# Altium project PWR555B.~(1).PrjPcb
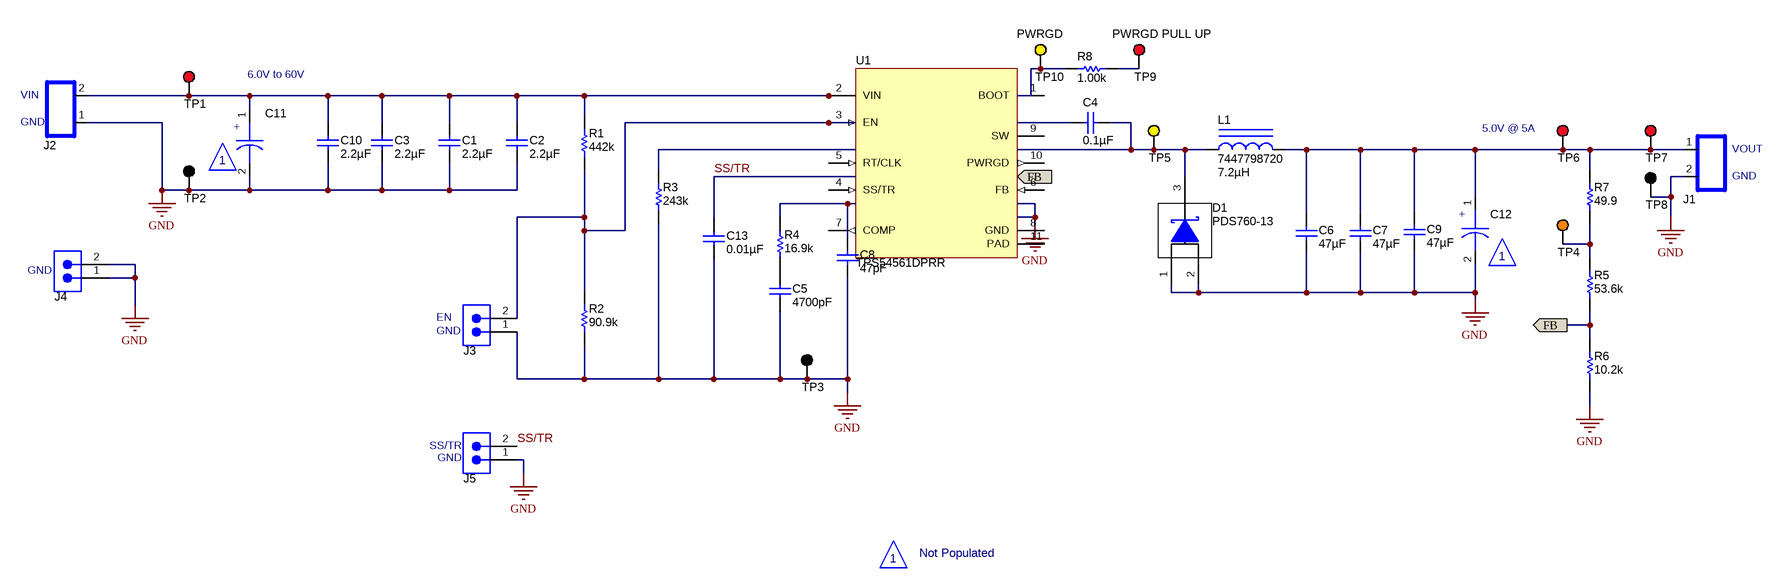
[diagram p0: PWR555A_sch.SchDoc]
CopyrightYear: 2013; PCB_Layout: Anthony Fagnani; PCB_Rev: A; PRJ_Customer: Public Release; PRJ_Engineer: Anthony Fagnani; PRJ_Number: PWR555; PRJ_Title: TPS54x61/x41EVM-555; SCH_Rev: A; TechSupport: http://www.ti.com/support
2 sheets, 58 parts. Net scope: flat (ports and power ports of the same name join across sheets).
Board file: PWR555A_pcb.PcbDoc
Sheets:
  PWR555A_sch.SchDoc
  PWR555A_hdwr.SchDoc

## Sheet PWR555A_sch.SchDoc
size 431 x 279 mm; Date: Not shown in title block; ApprovedBy: Not shown in title block; CheckedBy: Not shown in title block; Author: Not shown in title block; CompanyName: Not shown in title block; DrawnBy: Terry Dillard; Engineer: Steve Schnier; Organization: Not shown in title block; Address1: Not shown in title block; Address2: Not shown in title block; Address3: Not shown in title block; Address4: Not shown in title block; DocumentNumber: 1; Revision: Use project parameter SCH_Rev; SheetNumber: 1; SheetTotal: 2; PageSetup: Record=PageOptions¦CenterHorizontal=True¦CenterVertical=True¦PrintScale=1.00¦XCorrection=1.00¦YCorrection=1.00¦PrintKind=0¦BorderSize=5000000¦LeftOffset=0¦BottomOffset=0¦Orientation=2¦PaperLength=1000¦PaperWidth=1000¦Scale=100¦PaperSource=15¦PrintQuality=600¦MediaType=1¦DitherType=10¦PaperKind=Letter¦PrintScaleMode=1

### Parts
C1  ValueDisplayed: 2.2µF  [1210]  (hidden comment: GRM32ER72A225KA35L)
C2  ValueDisplayed: 2.2µF  [1210]  (hidden comment: GRM32ER72A225KA35L)
C3  ValueDisplayed: 2.2µF  [1210]  (hidden comment: GRM32ER72A225KA35L)
C4  ValueDisplayed: 0.1µF  [0603]  (hidden comment: C0603C104K8RACTU)
C5  ValueDisplayed: 4700pF  [0603]  (hidden comment: C0603C472J5RACTU)
C6  ValueDisplayed: 47µF  [1210]  (hidden comment: GRM32ER61C476ME15L)
C7  ValueDisplayed: 47µF  [1210]  (hidden comment: GRM32ER61C476ME15L)
C8  ValueDisplayed: 47pF  [0603]  (hidden comment: 06035A470JAT2A)
C9  ValueDisplayed: 47µF  [1210]  (hidden comment: GRM32ER61C476ME15L)
C10  ValueDisplayed: 2.2µF  [1210]  (hidden comment: GRM32ER72A225KA35L)
C11  Engineering Only  [C_SM-1210/E_TH-F]  (value not drawn)
C12  Engineering Only  [C_SM-1210/E_TH-F]  (value not drawn)
C13  ValueDisplayed: 0.01µF  [0603]  (hidden comment: C0603C103K5RACTU)
D1  PDS760-13  [PowerDI5]
J1  TBLK_15A_2X5.1MM  [TB_2X5.1MM]  (value not drawn)
J2  TBLK_15A_2X5.1MM  [TB_2X5.1MM]  (value not drawn)
J3  TSW-102-07-G-S  [TSW-102-07-G-S]  (value not drawn)
J4  TSW-102-07-G-S  [TSW-102-07-G-S]  (value not drawn)
J5  TSW-102-07-G-S  [TSW-102-07-G-S]  (value not drawn)
L1  7447798720  ValueDisplayed: 7.2µH  [WE-PDF_1064]
R1  value 442k  [0603]  (hidden comment: CRCW0603442KFKEA)
R2  value 90.9k  [0603]  (hidden comment: CRCW060390K9FKEA)
R3  value 243k  [0603]  (hidden comment: CRCW0603243KFKEA)
R4  value 16.9k  [0603]  (hidden comment: CRCW060316K9FKEA)
R5  value 53.6k  [0603]  (hidden comment: CRCW060353K6FKEA)
R6  value 10.2k  [0603]  (hidden comment: CRCW060310K2FKEA)
R7  value 49.9  [0603]  (hidden comment: CRCW060349R9FKEA)
R8  value 1.00k  [0603]  (hidden comment: CRCW06031K00FKEA)
TP1  5010  [Keystone5010]  (value not drawn)
TP2  5011  [Keystone5011]  (value not drawn)
TP3  5011  [Keystone5011]  (value not drawn)
TP4  5013  [Keystone5013]  (value not drawn)
TP5  5014  [Keystone5014]  (value not drawn)
TP6  5010  [Keystone5010]  (value not drawn)
TP7  5010  [Keystone5010]  (value not drawn)
TP8  5011  [Keystone5011]  (value not drawn)
TP9  5010  [Keystone5010]  (value not drawn)
TP10  5014  [Keystone5014]  (value not drawn)
U1  TPS54561DPRR  [DPR0010A]

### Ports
FB (in), FB (out)

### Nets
GND: C1.2 C2.2 C3.2 C5.2 C6.2 C7.2 C8.2 C9.2 C10.2 C11.2 C12.2 C13.2 D1.1(A) D1.2(A) J1.2 J2.1 J3.1 J4.1 J4.2 J5.1 R2.1 R3.1 R6.1 TP2.1 TP3.1 TP8.1
FB: R5.1 R6.2 ; port FB
SS/TR: C13.1 J5.2
NetC1_1: C1.1 C2.1 C3.1 C10.1 C11.1 J2.2 R1.2 TP1.1 U1.2(VIN)
NetC4_1: C4.1 D1.3(K) L1.1 TP5.1
NetC5_1: C5.1 R4.1
NetC6_1: C6.1 C7.1 C9.1 C12.1 J1.1 L1.2 R7.2 TP6.1 TP7.1
NetC8_1: C8.1 R4.2
NetJ3_2: J3.2 R1.1 R2.2 U1.3(EN)
NetR5_2: R5.2 R7.1 TP4.1
NetR8_1: R8.1 TP10.1
NetR8_2: R8.2 TP9.1

Not connected (* = marked no-connect by the designer): C4 2; R3 2; U1 1(BOOT) 4(SS/TR) 5(RT/CLK) 6(FB) 7(COMP) 8(GND) 9(SW) 10(PWRGD) 11(PAD)

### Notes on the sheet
- 6.0V to 60V
- (near TP10) PWRGD
- (near TP9) PWRGD PULL UP
- (near J2) VIN
- (near J2) GND
- (near TP6) 5.0V @ 5A
- 1
- (near J1) VOUT
- (near J1) GND
- (near J4) GND
- (near C12) 1
- (near J3) EN
- (near J3) GND
- (near J5) SS/TR
- (near J5) GND
- Not Populated

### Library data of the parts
C1-C3 C10 = GRM32ER72A225KA35L: CAP, CERM, 2.2uF, 100V, +/-10%, X7R, 1210; Manufacturer: MuRata; Polarized: N; CompType: Capacitor; U/M: EA; Cap_F: 0.0000022; Tolerance_%: 10; ESR_Ohm: 0.007; Value1: 0.007 ohm; VDC_V: 100; IRMS_A: 4.4; TaMin_C: -55; TaMax_C: 125
C4 = C0603C104K8RACTU: CAP, CERM, 0.1uF, 10V, +/-10%, X7R, 0603; Manufacturer: Kemet; Polarized: N; CompType: Capacitor; U/M: EA; Cap_F: 0.0000001; Tolerance_%: 10; TaMin_C: -55; TaMax_C: 125
C5 = C0603C472J5RACTU: CAP, CERM, 4700pF, 50V, +/-5%, X7R, 0603; Manufacturer: Kemet; Polarized: N; CompType: Capacitor; U/M: EA; Cap_F: 0.0000000047; Tolerance_%: 5; VDC_V: 50; TaMin_C: -55; TaMax_C: 125
C6 C7 C9 = GRM32ER61C476ME15L: CAP, CERM, 47uF, 16V, +/-20%, X5R, 1210; Manufacturer: MuRata; Polarized: N; CompType: Capacitor; U/M: EA; Cap_F: 0.000047; Tolerance_%: 20; ESR_Ohm: 0.002; Value1: 0.002 ohm; VDC_V: 16; TaMin_C: -55; TaMax_C: 85
C8 = 06035A470JAT2A: CAP, CERM, 47pF, 50V, +/-5%, C0G/NP0, 0603; Manufacturer: AVX; Polarized: N; CompType: Capacitor; U/M: EA; Cap_F: 0.000000000047; Tolerance_%: 5; ESR_Ohm: 0.174; Value1: 0.174 ohm; VDC_V: 50; TaMin_C: -55; TaMax_C: 125
C11 C12 = C-MULTI_1210-F: Capacitor, Aluminum, vvV, 20%; Manufacturer: {MFR}; Alternate Manufacturer: Any; Alternate PartNumber: Equivalent; Area: 168100; Value: {Value}
C13 = C0603C103K5RACTU: CAP, CERM, 0.01uF, 50V, +/-10%, X7R, 0603; Manufacturer: Kemet; Polarized: N; CompType: Capacitor; U/M: EA; Cap_F: 0.00000001; Tolerance_%: 10; Value1: Unknown; VDC_V: 50; TaMin_C: -55; TaMax_C: 125
D1 = PDS560-13: Diode, Schottky, 60V, 7A, PowerDI5; Manufacturer: Diodes Inc.; U/M: EA; Vf_V: 0.56; Io_A: 7; Vr_V: 60; Value2: 0.56V; TJmax_C: 150
J1 J2 = TBLK_15A_2X5.1MM: Terminal Block, 2-pin, 15-A, 5.1mm; Manufacturer: OST; PartNumber: ED120/2DS; Alternate Manufacturer: Any; Alternate PartNumber: Equivalent; area: 141600; Value: ED120/2DS
J3-J5 = TSW-102-07-G-S: Header, TH, 100mil, 2x1, Gold plated, 230 mil above insulator; Manufacturer: Samtec, Inc.; U/M: EA
L1 = 7447798720: Inductor, Shielded, Metal Composite, 7.2uH, 6A, 0.0113 ohm, SMD; Manufacturer: Wurth Elektronik eiSos; Ind_H: 7.2E-6; Imax_A: 6; Irms: 7.9A @ 40C rise; Isat: 6A @ 10% inductance drop; DCR_ohm: 0.0113; U/M: EA
R1 = CRCW0603442KFKEA: RES, 442k ohm, 1%, 0.1W, 0603; Manufacturer: Vishay-Dale; Alternate Manufacturer: Any; Alternate PartNumber: Equivalent; CompType: Resistor; Res_ohm: 442000; Tolerance_%: 1; Power_W: 0.1; VDC_V: 75; TempCo: 100 ppm/C; EIA_Code: E96; U/M: EA
R2 = CRCW060390K9FKEA: RES, 90.9k ohm, 1%, 0.1W, 0603; Manufacturer: Vishay-Dale; Alternate Manufacturer: Any; Alternate PartNumber: Equivalent; CompType: Resistor; Res_ohm: 90900; Value_Code: 90k9; Tolerance_%: 1; Power_W: 0.1; VDC_V: 75; TempCo: 100 ppm/C; EIA_Code: E96; U/M: EA
R3 = CRCW0603243KFKEA: RES, 243k ohm, 1%, 0.1W, 0603; Manufacturer: Vishay-Dale; Alternate Manufacturer: Any; Alternate PartNumber: Equivalent; CompType: Resistor; Res_ohm: 243000; Tolerance_%: 1; Power_W: 0.1; VDC_V: 75; TempCo: 100 ppm/C; EIA_Code: E96; U/M: EA
R4 = CRCW060316K9FKEA: RES, 16.9k ohm, 1%, 0.1W, 0603; Manufacturer: Vishay-Dale; Alternate Manufacturer: Any; Alternate PartNumber: Equivalent; CompType: Resistor; Res_ohm: 16900; Value_Code: 16k9; Tolerance_%: 1; Power_W: 0.1; VDC_V: 75; TempCo: 100 ppm/C; EIA_Code: E96; U/M: EA
R5 = CRCW060353K6FKEA: RES, 53.6k ohm, 1%, 0.1W, 0603; Manufacturer: Vishay-Dale; Alternate Manufacturer: Any; Alternate PartNumber: Equivalent; CompType: Resistor; Res_ohm: 53600; Value_Code: 53k6; Tolerance_%: 1; Power_W: 0.1; VDC_V: 75; TempCo: 100 ppm/C; EIA_Code: E96; U/M: EA
R6 = CRCW060310K2FKEA: RES, 10.2k ohm, 1%, 0.1W, 0603; Manufacturer: Vishay-Dale; Alternate Manufacturer: Any; Alternate PartNumber: Equivalent; CompType: Resistor; Res_ohm: 10200; Value_Code: 10k2; Tolerance_%: 1; Power_W: 0.1; VDC_V: 75; TempCo: 100 ppm/C; EIA_Code: E96; U/M: EA
R7 = CRCW060349R9FKEA: RES, 49.9 ohm, 1%, 0.1W, 0603; Manufacturer: Vishay-Dale; Alternate Manufacturer: Any; Alternate PartNumber: Equivalent; CompType: Resistor; Value_Code: 49R9; Tolerance_%: 1; Power_W: 0.1; VDC_V: 75; TempCo: 100 ppm/C; EIA_Code: E96; U/M: EA
R8 = CRCW06031K00FKEA: RES, 1.00k ohm, 1%, 0.1W, 0603; Manufacturer: Vishay-Dale; CompType: Resistor; Res_ohm: 1000; Value_Code: 1k00; Tolerance_%: 1; Power_W: 0.1; VDC_V: 75; TempCo: 100 ppm/C; EIA_Code: E96; U/M: EA
TP1 TP6 TP7 TP9 = 5010: Test Point, TH, Multipurpose, Red; Manufacturer: Keystone; CompType: Test Point Loop; U/M: EA
TP2 TP3 TP8 = 5011: Test Point, TH, Multipurpose, Black; Manufacturer: Keystone; CompType: Test Point Loop; U/M: EA
TP4 = 5013: Test Point, TH, Multipurpose, Orange; Manufacturer: Keystone; CompType: Test Point Loop; U/M: EA
TP5 TP10 = 5014: Test Point, TH Multipurpose, Yellow; Manufacturer: Keystone; CompType: Test Point Loop; U/M: EA
U1 = TPS54561DPRR: 60 V Input, 5 A, Step Down DC-DC Converter with Soft-Start and Eco-mode, DPR0010A; Alternate Manufacturer: Texas Instruments; Alternate PartNumber: TPS54561DPRT; SymbolCreator: a0411947; CompType: IC; U/M: EA

## Sheet PWR555A_hdwr.SchDoc: Aries 2
size 431 x 279 mm; Date: Not shown in title block; ApprovedBy: Not shown in title block; CheckedBy: Not shown in title block; Author: Not shown in title block; CompanyName: Not shown in title block; DrawnBy: Terry Dillard; Engineer: Steve Schnier; Organization: Not shown in title block; Address1: Not shown in title block; Address2: Not shown in title block; Address3: Not shown in title block; Address4: Not shown in title block; DocumentNumber: 3; SheetNumber: 2; SheetTotal: 2; PageSetup: Record=PageOptions|CenterHorizontal=True|CenterVertical=True|PrintScale=1.00|XCorrection=1.00|YCorrection=1.00|PrintKind=0|BorderSize=5000000|LeftOffset=0|BottomOffset=0|Orientation=2|PaperLength=1000|PaperWidth=1000|Scale=100|PaperSource=15|PrintQuality=600|MediaType=1|DitherType=10|PaperKind=Letter|PrintScaleMode=1
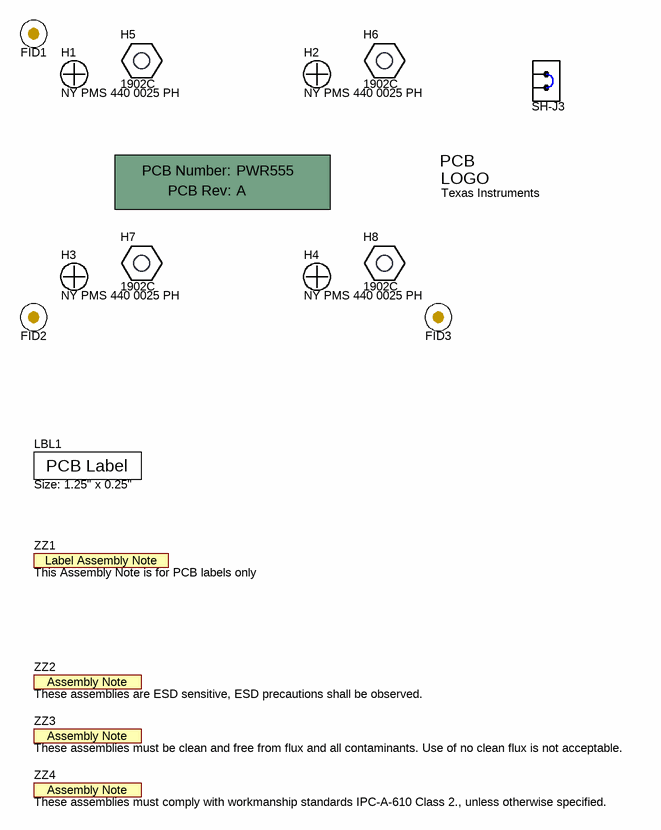
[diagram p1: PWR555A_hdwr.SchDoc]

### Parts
!PCB  Printed Circuit Board  (value not drawn)  (mechanical)
FID1  Fiducial  [Fiducial10-20]  (value not drawn)
FID2  Fiducial  [Fiducial10-20]  (value not drawn)
FID3  Fiducial  [Fiducial10-20]  (value not drawn)
H1  NY PMS 440 0025 PH  [NY PMS 440 0025 PH]
H2  NY PMS 440 0025 PH  [NY PMS 440 0025 PH]
H3  NY PMS 440 0025 PH  [NY PMS 440 0025 PH]
H4  NY PMS 440 0025 PH  [NY PMS 440 0025 PH]
H5  1902C  [Keystone_1902C]
H6  1902C  [Keystone_1902C]
H7  1902C  [Keystone_1902C]
H8  1902C  [Keystone_1902C]
LBL1  Size: 1.25" x 0.25"  [Label_1250x250]
Logo1  Texas Instruments  [TI_Stacked_Overlay_Medium]  (no BOM)
SH-J3  SNT-100-BK-G  [SNT-100-BK-G]  (value not drawn)
ZZ1  This Assembly Note is for PCB labels only  [AssemblyNoteLabel]  (no BOM)
ZZ2  These assemblies are ESD sensitive, ESD precautions shall be observed.  [AssemblyNote]  (no BOM)
ZZ3  These assemblies must be clean and free from flux and all contaminants. Use of no clean flux is not acceptable.  [AssemblyNote]  (no BOM)
ZZ4  These assemblies must comply with workmanship standards IPC-A-610 Class 2., unless otherwise specified.  [AssemblyNote]  (no BOM)

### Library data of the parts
!PCB = PCB: Manufacturer: Any; PartNumber: PWR555; SymbolCreator: a0412235
FID1-FID3 = Fiducial: Fiducial mark.  There is nothing to buy or mount.; SymbolCreator: codlsc
H1-H4 = NY PMS 440 0025 PH: Machine Screw, Round, #4-40 x 1/4, Nylon, Philips panhead; Manufacturer: B&F Fastener Supply; CompType: Hardware; SymbolCreator: codlsc; U/M: EA
H5-H8 = 1902C: Standoff, Hex, 0.5"L #4-40 Nylon; Manufacturer: Keystone; CompType: Hardware
LBL1 = THT-13-457-10: Thermal Transfer Printable Labels, 1.250" W x 0.250" H - 10,000 per roll; Manufacturer: Brady; SymbolCreator: a0412235; CompType: Label
Logo1 = TI_Logo: Texas Instrument Corporate Signature; SymbolCreator: codlsc
SH-J3 = SNT-100-BK-G: Shunt, 100mil, Gold plated, Black; Manufacturer: Samtec; Alternate Manufacturer: 3M; Alternate PartNumber: 969102-0000-DA; Value: 1x2; Note: You can "mate" this to a header by matching the designator.  i.e. use SH-J3 for header J3
ZZ1 = AssemblyNoteLabel: SymbolCreator: a0412235
ZZ2-ZZ4 = AssemblyNote: SymbolCreator: codlsc

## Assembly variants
001: not fitted C11 C12 FID1 FID2 FID3 H1 H2 H3 H4 H5 H6 H7 H8
002: not fitted C3 C9 C10 C11 C12 FID1 FID2 FID3 H1 H2 H3 H4 H5 H6 H7 H8
003: not fitted C9 C11 C12 FID1 FID2 FID3 H1 H2 H3 H4 H5 H6 H7 H8
004: not fitted C3 C7 C9 C10 C11 C12 FID1 FID2 FID3 H1 H2 H3 H4 H5 H6 H7 H8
